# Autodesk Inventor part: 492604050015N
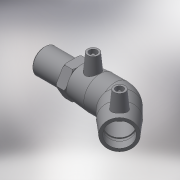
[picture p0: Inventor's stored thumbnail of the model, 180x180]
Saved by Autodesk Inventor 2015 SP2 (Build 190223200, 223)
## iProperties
Created: 2017-06
Part Number: 492604050015N
Material: Generic
Description: PLASSON 45° ELBOW TRANSITION MALE 50 x 1 1⁄2"
Document SubType Name: Modeling
Designer: KIM
Mass: 326.097 g
Surface Area: 676.08 cm^2
Volume: 326.097 cm^3
Density: 1 g/cm^3
Appearance: Default
Author: KIM
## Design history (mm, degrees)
derived "492604.ipt"
feature "Solid1::492604.ipt"
tag "TaggingFeature1"
body "Solid1"
other parameters: "d2" = 67, "d4" = 30.5, "d5" = 60.3, "d8" = 168 deg, "d10" = 19.6, "d11" = 6.53333, "d29" = 52, "d30" = 15, "d31" = 42.7, "d34" = 5 deg, "d41" = 4, "d42" = 14, "d43" = 0, "d50" = 32.5, "d51" = 19.6, "d52" = 50.47, "d54" = 135 deg, "d86" = 30.15, "d87" = 135 deg, "d88" = 122, "d90" = 49, "d91" = 0, "d92" = 49, "d93" = 0, "d101" = 3, "d102" = 0, "d107" = 0.1, "d108" = 35, "d109" = 47.803, "d110" = 63, "d111" = 15.75, "d112" = 67, "d113" = 33.4621, "d114" = 56.7, "d116" = 2.01, "d122" = 0, "d123" = 2.39015, "L_" = 185, "L_1" = 49, "D_" = 35, "A_" = 52, "d_2" = 12, "L_2" = 63, "R_" = 47.803, "D_1" = 67
